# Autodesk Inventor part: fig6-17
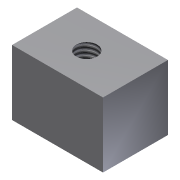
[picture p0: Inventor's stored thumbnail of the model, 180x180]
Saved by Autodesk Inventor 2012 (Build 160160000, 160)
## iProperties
Created: 2009-09
Part Number: fig6-17
Document SubType Name: Modeling
Designer: Sham
Density: 1 g/cm^3
Material: Default
Author: Sham
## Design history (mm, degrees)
sketch "Sketch1"
  geometry: L1 (-28, 20)-(0, 20); L2 (0, 20)-(0, 0); L3 (0, 0)-(-28, 0); L4 (-28, 0)-(-28, 20)
  constraints: 8 end point, 2 parallel, 1 horizontal, 1 perpendicular
extrude "Extrusion1" new body sketch "Sketch1" distance "d0" = 20; taper "d1" = 0 deg
hole "Hole1" diameter "d4" = 6.401; stored, may be unused: countersink angle "d8" = 90 deg, drill point angle "d10" = 118 deg; dims "d2" = 10, "d3" = 15, "d5" = 6, "d6" = 12, "d7" = 3, "d9" = 15
body "Solid1"
